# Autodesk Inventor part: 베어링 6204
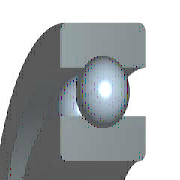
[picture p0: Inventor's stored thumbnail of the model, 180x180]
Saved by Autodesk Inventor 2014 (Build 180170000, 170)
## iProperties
IsCustomPart: 0
Created: 2009-02
Part Number: 베어링 6204
Material: 강, 연강
Description: 깊은 그루브 볼 베어링
Document SubType Name: Modeling
Standard: KS B 2023
Designer: KYOUNG IL JANG
Standards Organization: KS
Language: ko-KR
Size Designation: 6204 - 20 x 47 x 14
Categories: <MemberInstance><Categories><Category DisplayName="샤프트 부품" InternalName="7f7aeb1f-a693-4053-b835-cee3144e0d98" Mnemonic="SHFT"><Category DisplayName="베어링" Inter
Density: 7.86 g/cm^3
Mass: 104.255 g
Surface Area: 87.8912 cm^2
Volume: 13.264 cm^3
Appearance: 강철
Author: KYOUNG IL JANG
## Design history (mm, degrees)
sketch "스케치" dims "d0" = 7.02 (= -0.26 x WD + 0.26 x BD)
  geometry: L1 (3.49, 16.75)-(10.51, 16.75); L2 (7, 16.75)-(7, 13.24); L3 (7, 16.75)-(7, 20.26); L4 (4.392, 14.401)-(0, 14.401); L5 (0, 10)-(14, 10); L6 (4.392, 19.099)-(0, 19.099); L7 (0, 23.5)-(14, 23.5); L8 (14, 10)-(14, 14.401); L9 (9.608, 14.401)-(14, 14.401); L10 (9.608, 19.099)-(14, 19.099); L11 (14, 23.5)-(14, 19.099); L12 (-1.4, 0)-(8.4, 0) reference; L13 (0, -0.3)-(0, 5.3) reference
  constraints: 22 end point, 4 point on line, 2 collinear, 2 perpendicular, 2 symmetric about line, 1 midpoint, 1 parallel, 14 other
  dimensions: "d9" = 20 diameter of L5 L12 (= WD); "d11" = 47 diameter of L7 L12 (= BD); "d12" = 14 distance between parallel lines of L8 L13 (= KB); "d13" = 28.802 diameter of L9 L12 (= 0.326 x BD + 0.674 x WD)
revolve "본체" stored, may be unused: angle "d6" = 90 deg
revolve "볼" stored, may be unused: angle "d7" = 90 deg
pattern_circular "IDS_ARRAYBALL[SIMPL:T]" dims angle "d3" = 360 deg
body "Solid1"
fillet "모깎기1" dims "d1" = 1 (= KRS)
other parameters: "WD" = 20 [user parameter; used in 5 equation terms], "BD" = 47 [user parameter; used in 5 equation terms], "KB" = 14 [user parameter; used in 1 equation term], "KRS" = 1 [user parameter; used in 1 equation term], "d4" = 0, "d5" = 0, "d8" = 0, "d14" = 0, "d15" = 0, "BBA" = 0 [user parameter], "BC0" = 6550000 [user parameter], "BC" = 1.27e+07 [user parameter], "BR" = 23.5 (= 0.5 x BD) [user parameter]
